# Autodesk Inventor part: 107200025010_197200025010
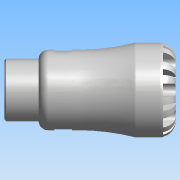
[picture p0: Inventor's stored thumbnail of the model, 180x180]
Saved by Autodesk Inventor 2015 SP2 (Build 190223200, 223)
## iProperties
Created: 2016-12
Part Number: 107200025010_197200025010
Material: PVC-Piping
Description: PLASSON MALE INTEGRAL BRASS THREAD 25X1" SERIES 1
Document SubType Name: Modeling
Designer: KIM
Mass: 61.7504 g
Surface Area: 140.097 cm^2
Volume: 44.1074 cm^3
Density: 1.4 g/cm^3
Appearance: Smooth - White
Author: KIM
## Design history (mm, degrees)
derived "1072.ipt"
feature "Solid1::1072.ipt"
tag "TaggingFeature1"
body "Solid1"
other parameters: "d0" = 85, "d1" = 20.16, "d2" = 25, "d3" = 31.25, "d4" = 47, "d6" = 48, "d8" = 39.95, "d13" = 6.3, "d14" = 6.3, "d15" = 0, "d17" = 360 deg, "d19" = 8 deg, "d20" = 0.5, "d21" = 0.5, "d22" = 8 deg, "d24" = 0, "d26" = 360 deg, "d32" = 4.7, "d33" = 4.7, "d34" = 30.931, "d38" = 17, "d39" = 0.92793, "d42" = 8.75, "d43" = 5.75, "d45" = 12.348, "d46" = 0, "d59" = 360 deg, "d61" = 7.4375, "d62" = 0.5, "d64" = 0, "d65" = 0.47, "d68" = 3.57143, "d_" = 25, "E_" = 47, "H_" = 85, "l_" = 48, "R_" = 30.931, "l_2" = 17, "d9" = 7.875, "d11" = 47, "d12" = 31.25
